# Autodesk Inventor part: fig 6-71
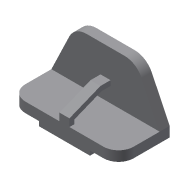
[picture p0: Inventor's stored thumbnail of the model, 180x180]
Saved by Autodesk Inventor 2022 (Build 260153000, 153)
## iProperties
Created: 2001-12
Part Number: fig 6-71
Document SubType Name: Modeling
Designer: Renu Muthoo
Density: 1 g/cm^3
Material: Generic
Appearance: Default
Control State: 0
Master: False
Checked Out: False
Shininess: 77.0
Length Units: 11269
Angle Units: 11279
Time Units: 11290
Mass Units: 11283
Length Display Precision: 3
Angle Display Precision: 2
Density: 0.0
Volumn: 0.0
Area: 0.0
PropertySet Name: Model Information
Author: Renu Muthoo
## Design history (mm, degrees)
sketch "Sketch2"
  geometry: L1 (-67.219, 19.116)-(148.781, 19.116); L2 (148.781, 19.116)-(148.781, -0.884); L3 (-67.219, -0.884)-(-67.219, 19.116); L4 (-10.219, -0.884)-(-10.219, -9.884); L5 (-10.219, -9.884)-(91.781, -9.884); L6 (91.781, -9.884)-(91.781, -0.884); L7 (148.781, -0.884)-(91.781, -0.884); L8 (-10.219, -0.884)-(-67.219, -0.884)
  constraints: 16 end point, 5 parallel, 4 perpendicular, 2 equal length, 1 horizontal
  dimensions: "d0" = 102 distance of L4.end L5.end; "d1" = 57 distance of L4.start L3.start; "d2" = 29 distance between parallel lines of L1 L5; "d3" = 20 distance of L1.end L2.end
extrude "Extrusion1" new body sketch "Sketch2" distance "d4" = 102; taper "d5" = 0 deg
sketch "Sketch3"
  geometry: L1 (67.219, -19.116)-(-148.781, -19.116) reference; L2 (67.219, -19.116)-(31.475, -93.564); L3 (-2.781, -115.116)-(-78.781, -115.116); L4 (-113.038, -93.564)-(-148.781, -19.116); A1 r 38 centre (-2.781, -77.116) between (-2.781, -115.116) and (31.475, -93.564); A2 r 38 centre (-78.781, -77.116) between (-113.038, -93.564) and (-78.781, -115.116)
  constraints: 6 end point, 4 point on circle, 4 tangent, 2 centre point, 1 equal length, 1 equal radius, 1 parallel
  dimensions: "d6" = 96 distance between parallel lines of L3 L1; "d7" = 38 radius of A1; "d8" = 76 distance of A2.centre A1.centre
extrude "Extrusion2" join sketch "Sketch3" distance "d9" = 20; taper "d10" = 0 deg
fillet "Fillet1" dims "d11" = 30
workplane "Work Plane1"
sketch "Sketch7"
  geometry: L1 (0, -82)-(-15, -82); L2 (-15, -82)-(-40, -20); L3 (-40, -20)-(-40, 0); L4 (0, -82)-(20, -82) reference; L5 (0, 0)-(-74.447, 0) reference
  constraints: 6 end point, 2 point on line, 1 horizontal, 1 perpendicular
  dimensions: "d32" = 20 distance of L2.end L3.end; "d33" = 15 distance of L1.start L1.end; "d34" = 40 distance of L5.start L3.end
feature "Rib4" sketch "Sketch7" dims "d55" = 10, "d56" = 20, "d57" = 0
body "Solid1"
other parameters: "d12" = -108
